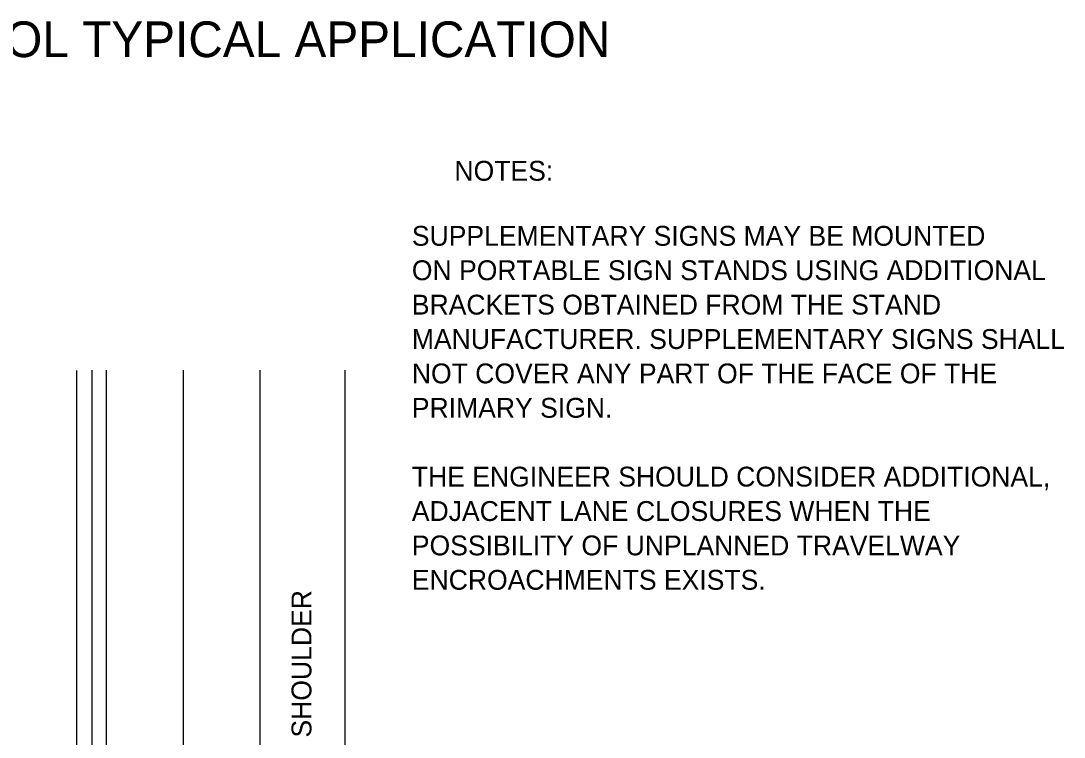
# Model space of a CAD drawing. Extents: x 612.48 to 619.85, y 611.03 to 621.01.
# Drawn here: x 616.048 to 619.203, y 618.847 to 621.013 of the extents above; entities that cross this region are included whole.
import ezdxf

# ---------------------------------------------------------------- set-up
doc = ezdxf.new("R2010")
doc.units = 0
for name, color, linetype in [('DETL-LINE', 7, 'Continuous'), ('DETL-NOTE', 7, 'Continuous'), ('DETL-TITL', 7, 'Continuous')]:
    doc.layers.add(name, color=color, linetype=linetype)

msp = doc.modelspace()

# ---------------------------------------------------------------- linework, layer by layer
at = {"layer": 'DETL-LINE'}
for p, q in [((616.2167, 619.9558), (616.2167, 613.1041)), ((616.2629, 619.9564), (616.2629, 613.1045)), ((616.2629, 619.9564), (616.2629, 613.1045)), ((616.306, 619.9564), (616.306, 613.1045)), ((616.5386, 619.9564), (616.5386, 613.1045)), ((616.771, 619.9564), (616.771, 613.1045)), ((617.0282, 619.9564), (617.0282, 615.9413))]:
    msp.add_line(p, q, dxfattribs=at)
for points in [[(616.5386, 619.8064), (616.5386, 619.7064)], [(616.5386, 619.4064), (616.5386, 619.3064)], [(616.5386, 619.0064), (616.5386, 618.9064)]]:
    msp.add_lwpolyline(points, dxfattribs=at)

# ---------------------------------------------------------------- texts
at = {"layer": 'DETL-NOTE'}
for s, p in [('NOTES:', (617.3592, 620.5295)), ('SUPPLEMENTARY SIGNS MAY BE MOUNTED', (617.2304, 620.3328)), ('ON PORTABLE SIGN STANDS USING ADDITIONAL ', (617.2304, 620.2288)), ('BRACKETS OBTAINED FROM THE STAND ', (617.2304, 620.1248)), ('MANUFACTURER. SUPPLEMENTARY SIGNS SHALL ', (617.2304, 620.0208)), ('NOT COVER ANY PART OF THE FACE OF THE ', (617.2304, 619.9168)), ('PRIMARY SIGN.', (617.2304, 619.8128)), ('THE ENGINEER SHOULD CONSIDER ADDITIONAL, ', (617.2304, 619.6048)), ('ADJACENT LANE CLOSURES WHEN THE ', (617.2304, 619.5008)), ('POSSIBILITY OF UNPLANNED TRAVELWAY', (617.2304, 619.3968)), ('ENCROACHMENTS EXISTS.', (617.2304, 619.2928))]:
    msp.add_text(s, height=0.06, dxfattribs=at).set_placement(p)
msp.add_text('SHOULDER', height=0.06, rotation=90, dxfattribs=at).set_placement((616.9267, 618.846))
at = {"layer": 'DETL-TITL'}
msp.add_text('TEMPORARY TRAFFIC CONTROL TYPICAL APPLICATION', height=0.108, dxfattribs=at).set_placement((613.8826, 620.9031))

doc.saveas('drawing.dxf')
